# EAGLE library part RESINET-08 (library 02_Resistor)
Resistor Network(8) 8 peaces
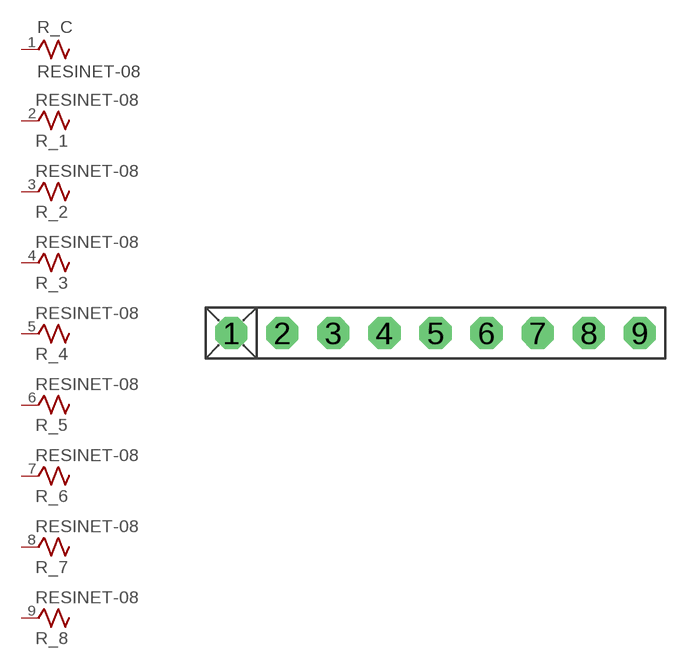
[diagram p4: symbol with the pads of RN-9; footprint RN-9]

Designator prefix R; gates _C=RESINET-COM _1=RESINET-X _2=RESINET-X _3=RESINET-X _4=RESINET-X _5=RESINET-X _6=RESINET-X _7=RESINET-X _8=RESINET-X

## RESINET-08  [RN-9]
1  _C:1  pas
2  _1:1  pas
3  _2:1  pas
4  _3:1  pas
5  _4:1  pas
6  _5:1  pas
7  _6:1  pas
8  _7:1  pas
9  _8:1  pas

## Footprint RN-9 (pad centres in mm)
Resistor Network(8) 8 peaces
drill 0.813 pad 1.6 octagon: 1 -10.16,0; 2 -7.62,0; 3 -5.08,0; 4 -2.54,0; 5 0,0; 6 2.54,0; 7 5.08,0; 8 7.62,0; 9 10.16,0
